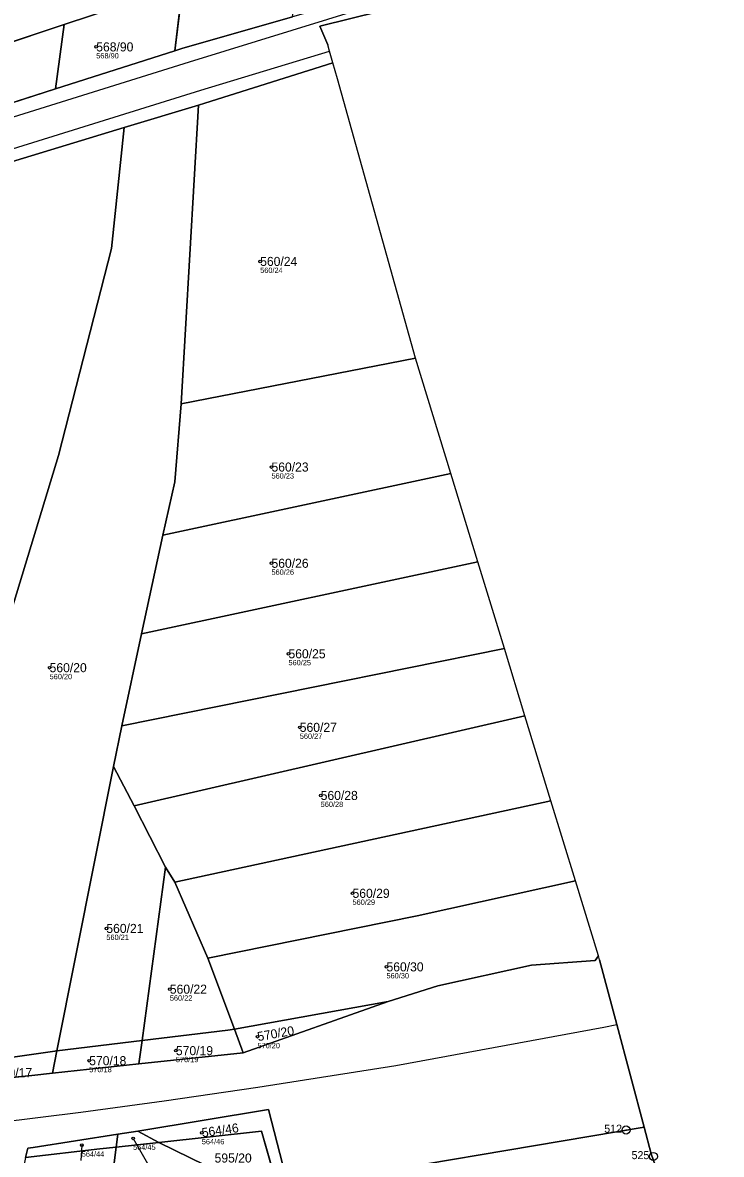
# Model space of a CAD drawing. Extents: x -732749 to -730903, y -1025757 to -1023435.
# Drawn here: x -731348.6 to -731217.7, y -1024807.5 to -1024595.4 of the extents above; entities that cross this region are included whole.
import ezdxf

# ---------------------------------------------------------------- set-up
doc = ezdxf.new("R2010")
doc.units = 0
for name, color, linetype in [('Definiční body', 7, 'Continuous'), ('Hranice parcel', 7, 'Continuous'), ('Parcelní čísla', 7, 'Continuous'), ('Polygon ku', 7, 'Continuous'), ('Polygon parcely', 7, 'Continuous'), ('Pop  PČ popisy', 7, 'Continuous'), ('Poz předměty', 7, 'Continuous'), ('Vnitřní kresba', 7, 'Continuous'), ('Značky bodu BP', 7, 'Continuous')]:
    doc.layers.add(name, color=color, linetype=linetype)

msp = doc.modelspace()

# ---------------------------------------------------------------- linework, layer by layer
at = {"layer": 'Definiční body'}
for centre in [(-731334.82, -1024599.96), (-731304.1, -1024640.16), (-731301.98, -1024678.69), (-731301.98, -1024696.72), (-731298.8, -1024713.68), (-731343.56, -1024716.29), (-731296.68, -1024727.47), (-731292.76, -1024740.23), (-731286.79, -1024758.57), (-731332.93, -1024765.15), (-731280.43, -1024772.35), (-731321.03, -1024776.53), (-731304.62, -1024785.44), (-731319.89, -1024788.05), (-731336.14, -1024789.93), (-731315.04, -1024803.44), (-731327.92, -1024804.49), (-731337.54, -1024805.77)]:
    msp.add_circle(centre, 0.25, dxfattribs=at)
at = {"layer": 'Hranice parcel'}
for p, q in [((-731340.83, -1024595.77), (-731320.55, -1024589.04)), ((-731320.09, -1024600.67), (-731318.62, -1024588.44)), ((-731298.04, -1024594.31), (-731318.77, -1024600.25)), ((-731361.64, -1024602.68), (-731340.83, -1024595.77)), ((-731342.46, -1024607.84), (-731340.83, -1024595.77)), ((-731292.9, -1024596.1), (-731291.4, -1024599.6)), ((-731320.09, -1024600.67), (-731342.46, -1024607.84)), ((-731318.77, -1024600.25), (-731320.09, -1024600.67)), ((-731314.47, -1024610.5), (-731290.46, -1024602.97)), ((-731289.63, -1024605.94), (-731290.46, -1024602.97)), ((-731275, -1024658.3), (-731289.63, -1024605.94)), ((-731342.46, -1024607.84), (-731363.18, -1024614.48)), ((-731329.57, -1024615.08), (-731315.68, -1024610.87)), ((-731318.88, -1024666.84), (-731315.68, -1024610.87)), ((-731315.68, -1024610.87), (-731314.47, -1024610.5)), ((-731275, -1024658.3), (-731318.88, -1024666.84)), ((-731268.38, -1024679.93), (-731275, -1024658.3)), ((-731322.32, -1024691.46), (-731268.38, -1024679.93)), ((-731263.32, -1024696.44), (-731268.38, -1024679.93)), ((-731326.35, -1024709.93), (-731322.32, -1024691.46)), ((-731263.32, -1024696.44), (-731326.35, -1024709.93)), ((-731258.34, -1024712.69), (-731263.32, -1024696.44)), ((-731330.02, -1024727.2), (-731326.35, -1024709.93)), ((-731330.02, -1024727.2), (-731258.34, -1024712.69)), ((-731254.48, -1024725.29), (-731258.34, -1024712.69)), ((-731327.73, -1024742.16), (-731254.48, -1024725.29)), ((-731249.6, -1024741.23), (-731254.48, -1024725.29)), ((-731331.6, -1024734.81), (-731330.02, -1024727.2)), ((-731342.2, -1024788.09), (-731331.6, -1024734.81)), ((-731327.73, -1024742.16), (-731331.6, -1024734.81)), ((-731320.09, -1024756.5), (-731249.6, -1024741.23)), ((-731245.01, -1024756.21), (-731249.6, -1024741.23)), ((-731321.84, -1024753.69), (-731327.73, -1024742.16)), ((-731326.23, -1024786.17), (-731321.84, -1024753.69)), ((-731320.09, -1024756.5), (-731321.84, -1024753.69)), ((-731313.93, -1024770.71), (-731320.09, -1024756.5)), ((-731240.7, -1024770.3), (-731245.01, -1024756.21)), ((-731308.92, -1024784.01), (-731313.93, -1024770.71)), ((-731240.5, -1024771.06), (-731240.7, -1024770.3)), ((-731240.5, -1024771.06), (-731237.27, -1024783.17)), ((-731308.92, -1024784.01), (-731280.11, -1024778.84)), ((-731280.11, -1024778.84), (-731307.26, -1024788.44)), ((-731326.23, -1024786.17), (-731310.19, -1024784.24)), ((-731310.19, -1024784.24), (-731308.92, -1024784.01)), ((-731307.26, -1024788.44), (-731308.92, -1024784.01)), ((-731237.27, -1024783.17), (-731232.14, -1024802.38)), ((-731342.2, -1024788.09), (-731326.23, -1024786.17)), ((-731326.82, -1024790.53), (-731326.23, -1024786.17)), ((-731343.03, -1024792.27), (-731342.2, -1024788.09)), ((-731307.26, -1024788.44), (-731326.82, -1024790.53)), ((-731326.82, -1024790.53), (-731343.03, -1024792.27)), ((-731346.88, -1024792.68), (-731370.02, -1024795.11)), ((-731343.03, -1024792.27), (-731346.88, -1024792.68)), ((-731330.8, -1024803.72), (-731327.03, -1024803.13)), ((-731323.1, -1024805.24), (-731327.03, -1024803.13)), ((-731323.1, -1024805.24), (-731303.84, -1024803.13)), ((-731303.84, -1024803.13), (-731300.76, -1024813.97)), ((-731232.14, -1024802.38), (-731298.8, -1024813.64)), ((-731331.11, -1024806.12), (-731330.8, -1024803.72)), ((-731331.11, -1024806.12), (-731323.1, -1024805.24)), ((-731299.88, -1024816.64), (-731323.1, -1024805.24)), ((-731334.18, -1024806.46), (-731348.06, -1024808.05)), ((-731331.11, -1024806.12), (-731334.18, -1024806.46))]:
    msp.add_line(p, q, dxfattribs=at)
for points in [[(-731000.56, -1024491.5), (-731019.19, -1024499.94), (-731038.5, -1024508.7), (-731067.06, -1024522.46), (-731108.1, -1024540.6), (-731132.9, -1024550.8), (-731231, -1024580.7), (-731292.9, -1024596.1)], [(-731290.46, -1024602.97), (-731291.08, -1024600.75), (-731291.4, -1024599.6)], [(-731329.57, -1024615.08), (-731360.81, -1024624.55), (-731373.64, -1024628.52)], [(-731369.39, -1024791.96), (-731354.94, -1024719.31), (-731341.91, -1024676.51), (-731331.96, -1024637.77), (-731329.57, -1024615.08)], [(-731322.32, -1024691.46), (-731320.12, -1024681.47), (-731318.88, -1024666.84)], [(-731313.93, -1024770.71), (-731274.67, -1024762.8), (-731245.01, -1024756.21)], [(-731240.7, -1024770.3), (-731241.32, -1024771.18), (-731253.24, -1024772.02), (-731270.83, -1024775.92), (-731280.11, -1024778.84)], [(-731369.39, -1024791.96), (-731342.59, -1024788.14), (-731342.37, -1024788.11), (-731342.2, -1024788.09)], [(-731327.03, -1024803.13), (-731302.56, -1024799.1), (-731298.8, -1024813.64)], [(-731232.14, -1024802.38), (-731230.8, -1024807.4), (-731228.6, -1024813.75)], [(-731348.06, -1024808.05), (-731347.62, -1024806.31), (-731346.66, -1024806.21), (-731330.8, -1024803.72)], [(-731332.37, -1024827.26), (-731333.74, -1024826.75), (-731331.11, -1024806.12)]]:
    msp.add_lwpolyline(points, dxfattribs=at)
at = {"layer": 'Polygon ku'}
msp.add_lwpolyline([(-731228.6, -1024813.75), (-731230.8, -1024807.4), (-731232.14, -1024802.38), (-731237.27, -1024783.17), (-731240.5, -1024771.06), (-731240.7, -1024770.3), (-731245.01, -1024756.21), (-731249.6, -1024741.23), (-731254.48, -1024725.29), (-731258.34, -1024712.69), (-731263.32, -1024696.44), (-731268.38, -1024679.93), (-731275, -1024658.3), (-731289.63, -1024605.94), (-731290.46, -1024602.97), (-731291.08, -1024600.75), (-731291.4, -1024599.6), (-731292.9, -1024596.1), (-731231, -1024580.7), (-731132.9, -1024550.8)], dxfattribs=at)
at = {"layer": 'Polygon parcely'}
for points in [[(-731396.92, -1024430.73), (-731405.68, -1024487.75), (-731408.32, -1024539.25), (-731411.17, -1024556.07), (-731428.58, -1024623.59), (-731409.79, -1024619.61), (-731404.24, -1024617.64), (-731379.95, -1024609.03), (-731367.75, -1024604.71), (-731361.64, -1024602.68), (-731340.83, -1024595.77), (-731320.55, -1024589.04), (-731296.11, -1024580.48), (-731268.95, -1024570.98), (-731263.25, -1024568.98), (-731247.73, -1024563.81), (-731245.2, -1024560.99), (-731237.03, -1024551.86), (-731219.11, -1024538.09), (-731199.3, -1024513.61)], [(-731507.81, -1024670.47), (-731487.83, -1024663.94), (-731481.06, -1024661.72), (-731464.74, -1024656.68), (-731440.17, -1024649.08), (-731417.24, -1024641.99), (-731416.66, -1024639.33), (-731394.43, -1024632.88), (-731394.88, -1024635.08), (-731373.64, -1024628.52), (-731360.81, -1024624.55), (-731329.57, -1024615.08), (-731315.68, -1024610.87), (-731314.47, -1024610.5), (-731290.46, -1024602.97), (-731291.08, -1024600.75), (-731291.4, -1024599.6), (-731292.9, -1024596.1), (-731231, -1024580.7), (-731132.9, -1024550.8)], [(-731200.51, -1024564.65), (-731223.17, -1024571.11), (-731236.65, -1024574.96), (-731247.44, -1024578.5), (-731271.49, -1024586.39), (-731279.07, -1024588.88), (-731298.04, -1024594.31), (-731318.77, -1024600.25), (-731320.09, -1024600.67), (-731342.46, -1024607.84), (-731363.18, -1024614.48), (-731364.5, -1024614.9), (-731381.78, -1024620.45), (-731406.87, -1024628.5), (-731418.04, -1024632.08), (-731431.49, -1024635.93), (-731452.35, -1024641.89), (-731458.9, -1024643.76), (-731474.7, -1024648.82), (-731495.41, -1024655.45), (-731510.51, -1024660.29)], [(-731348.06, -1024808.05), (-731347.62, -1024806.31), (-731346.66, -1024806.21), (-731330.8, -1024803.72), (-731327.03, -1024803.13), (-731302.56, -1024799.1), (-731298.8, -1024813.64), (-731232.14, -1024802.38), (-731237.27, -1024783.17), (-731240.5, -1024771.06), (-731240.7, -1024770.3), (-731241.32, -1024771.18), (-731253.24, -1024772.02), (-731270.83, -1024775.92), (-731280.11, -1024778.84), (-731307.26, -1024788.44), (-731326.82, -1024790.53), (-731343.03, -1024792.27), (-731346.88, -1024792.68), (-731370.02, -1024795.11)]]:
    msp.add_lwpolyline(points, dxfattribs=at)
for points in [[(-731296.25, -1024581.49), (-731318.62, -1024588.44), (-731320.09, -1024600.67), (-731318.77, -1024600.25), (-731298.04, -1024594.31)], [(-731318.62, -1024588.44), (-731320.55, -1024589.04), (-731340.83, -1024595.77), (-731342.46, -1024607.84), (-731320.09, -1024600.67)], [(-731342.46, -1024607.84), (-731340.83, -1024595.77), (-731361.64, -1024602.68), (-731363.18, -1024614.48)], [(-731275, -1024658.3), (-731289.63, -1024605.94), (-731290.46, -1024602.97), (-731314.47, -1024610.5), (-731315.68, -1024610.87), (-731318.88, -1024666.84)], [(-731342.2, -1024788.09), (-731331.6, -1024734.81), (-731330.02, -1024727.2), (-731326.35, -1024709.93), (-731322.32, -1024691.46), (-731320.12, -1024681.47), (-731318.88, -1024666.84), (-731315.68, -1024610.87), (-731329.57, -1024615.08), (-731331.96, -1024637.77), (-731341.91, -1024676.51), (-731354.94, -1024719.31), (-731369.39, -1024791.96), (-731342.59, -1024788.14), (-731342.37, -1024788.11)], [(-731369.79, -1024792.02), (-731369.39, -1024791.96), (-731354.94, -1024719.31), (-731341.91, -1024676.51), (-731331.96, -1024637.77), (-731329.57, -1024615.08), (-731360.81, -1024624.55), (-731373.64, -1024628.52), (-731374.96, -1024636.49), (-731382.25, -1024668.49), (-731399.92, -1024749.24), (-731405.96, -1024777.18), (-731409.81, -1024794.03), (-731398.19, -1024792.52)], [(-731268.38, -1024679.93), (-731275, -1024658.3), (-731318.88, -1024666.84), (-731320.12, -1024681.47), (-731322.32, -1024691.46)], [(-731263.32, -1024696.44), (-731268.38, -1024679.93), (-731322.32, -1024691.46), (-731326.35, -1024709.93)], [(-731258.34, -1024712.69), (-731263.32, -1024696.44), (-731326.35, -1024709.93), (-731330.02, -1024727.2)], [(-731254.48, -1024725.29), (-731258.34, -1024712.69), (-731330.02, -1024727.2), (-731331.6, -1024734.81), (-731327.73, -1024742.16)], [(-731249.6, -1024741.23), (-731254.48, -1024725.29), (-731327.73, -1024742.16), (-731321.84, -1024753.69), (-731320.09, -1024756.5)], [(-731321.84, -1024753.69), (-731327.73, -1024742.16), (-731331.6, -1024734.81), (-731342.2, -1024788.09), (-731326.23, -1024786.17)], [(-731245.01, -1024756.21), (-731249.6, -1024741.23), (-731320.09, -1024756.5), (-731313.93, -1024770.71), (-731274.67, -1024762.8)], [(-731308.92, -1024784.01), (-731313.93, -1024770.71), (-731320.09, -1024756.5), (-731321.84, -1024753.69), (-731326.23, -1024786.17), (-731310.19, -1024784.24)], [(-731240.7, -1024770.3), (-731245.01, -1024756.21), (-731274.67, -1024762.8), (-731313.93, -1024770.71), (-731308.92, -1024784.01), (-731280.11, -1024778.84), (-731270.83, -1024775.92), (-731253.24, -1024772.02), (-731241.32, -1024771.18)], [(-731307.26, -1024788.44), (-731280.11, -1024778.84), (-731308.92, -1024784.01)], [(-731307.26, -1024788.44), (-731308.92, -1024784.01), (-731310.19, -1024784.24), (-731326.23, -1024786.17), (-731326.82, -1024790.53)], [(-731326.23, -1024786.17), (-731342.2, -1024788.09), (-731343.03, -1024792.27), (-731326.82, -1024790.53)], [(-731342.2, -1024788.09), (-731342.37, -1024788.11), (-731342.59, -1024788.14), (-731369.39, -1024791.96), (-731370.02, -1024795.11), (-731346.88, -1024792.68), (-731343.03, -1024792.27)], [(-731323.1, -1024805.24), (-731303.84, -1024803.13), (-731300.76, -1024813.97), (-731298.8, -1024813.64), (-731302.56, -1024799.1), (-731327.03, -1024803.13)], [(-731323.1, -1024805.24), (-731327.03, -1024803.13), (-731330.8, -1024803.72), (-731331.11, -1024806.12)], [(-731299.88, -1024816.64), (-731300.76, -1024813.97), (-731303.84, -1024803.13), (-731323.1, -1024805.24)], [(-731300.76, -1024813.97), (-731299.88, -1024816.64), (-731296.44, -1024827.15), (-731294.01, -1024826.84), (-731228.6, -1024813.75), (-731230.8, -1024807.4), (-731232.14, -1024802.38), (-731298.8, -1024813.64)], [(-731330.8, -1024803.72), (-731346.66, -1024806.21), (-731347.62, -1024806.31), (-731348.06, -1024808.05), (-731334.18, -1024806.46), (-731331.11, -1024806.12)], [(-731299.88, -1024816.64), (-731323.1, -1024805.24), (-731331.11, -1024806.12), (-731333.74, -1024826.75), (-731332.37, -1024827.26), (-731291.14, -1024846.23), (-731295.29, -1024830.69), (-731296.44, -1024827.15)], [(-731374.34, -1024937.46), (-731356.44, -1024941.69), (-731352.12, -1024927.24), (-731348.72, -1024912.77), (-731345.62, -1024896.67), (-731342.59, -1024881.5), (-731335.27, -1024850.07), (-731332.37, -1024827.26), (-731333.74, -1024826.75), (-731331.11, -1024806.12), (-731334.18, -1024806.46), (-731348.06, -1024808.05)]]:
    msp.add_lwpolyline(points, close=True, dxfattribs=at)
at = {"layer": 'Pop  PČ popisy'}
for p, q in [((-731327.92, -1024804.49), (-731326.7, -1024806.58)), ((-731337.54, -1024805.77), (-731337.7, -1024808.62)), ((-731326.7, -1024806.58), (-731325.2, -1024809.18))]:
    msp.add_line(p, q, dxfattribs=at)
at = {"layer": 'Poz předměty'}
for p, q in [((-731278.68, -1024790.84), (-731239.67, -1024783.62)), ((-731239.67, -1024783.62), (-731237.27, -1024783.17)), ((-731304.55, -1024794.88), (-731278.68, -1024790.84)), ((-731322.07, -1024797.44), (-731304.55, -1024794.88)), ((-731337.72, -1024799.57), (-731322.07, -1024797.44)), ((-731360.83, -1024802.41), (-731337.72, -1024799.57))]:
    msp.add_line(p, q, dxfattribs=at)
at = {"layer": 'Vnitřní kresba'}
for p, q in [((-731317.34, -1024602.76), (-731278.86, -1024590.82)), ((-731315.23, -1024608.09), (-731291.08, -1024600.75)), ((-731363.54, -1024617.22), (-731317.34, -1024602.76)), ((-731361.97, -1024622.65), (-731315.23, -1024608.09))]:
    msp.add_line(p, q, dxfattribs=at)
at = {"layer": 'Značky bodu BP'}
for centre, radius in [((-731235.53, -1024802.92), 0.75), ((-731235.53, -1024802.92), 0.03), ((-731230.41, -1024807.88), 0.75)]:
    msp.add_circle(centre, radius, dxfattribs=at)

# ---------------------------------------------------------------- texts
at = {"layer": 'Definiční body'}
for s, p in [('568/90', (-731334.82, -1024602.12)), ('560/24', (-731304.1, -1024642.32)), ('560/23', (-731301.98, -1024680.85)), ('560/26', (-731301.98, -1024698.88)), ('560/25', (-731298.8, -1024715.84)), ('560/20', (-731343.56, -1024718.45)), ('560/27', (-731296.68, -1024729.63)), ('560/28', (-731292.76, -1024742.39)), ('560/29', (-731286.79, -1024760.73)), ('560/21', (-731332.93, -1024767.31)), ('560/30', (-731280.43, -1024774.51)), ('560/22', (-731321.03, -1024778.69)), ('570/20', (-731304.62, -1024787.6)), ('570/19', (-731319.89, -1024790.21)), ('570/18', (-731336.14, -1024792.09)), ('564/46', (-731315.04, -1024805.6)), ('564/44', (-731337.54, -1024807.93)), ('564/45', (-731327.92, -1024806.65))]:
    msp.add_text(s, height=1, dxfattribs=at).set_placement(p)
at = {"layer": 'Parcelní čísla'}
for s, p in [('568/90', (-731334.82, -1024600.81)), ('560/24', (-731304.1, -1024641.01)), ('560/23', (-731301.98, -1024679.54)), ('560/26', (-731301.98, -1024697.57)), ('560/25', (-731298.8, -1024714.53)), ('560/20', (-731343.56, -1024717.14)), ('560/27', (-731296.68, -1024728.32)), ('560/28', (-731292.76, -1024741.08)), ('560/29', (-731286.79, -1024759.42)), ('560/21', (-731332.93, -1024766)), ('560/30', (-731280.43, -1024773.2)), ('560/22', (-731321.03, -1024777.38)), ('570/19', (-731319.89, -1024788.9)), ('570/18', (-731336.14, -1024790.78)), ('570/17', (-731353.79, -1024793.03)), ('595/20', (-731312.64, -1024809.02))]:
    msp.add_text(s, height=1.7, dxfattribs=at).set_placement(p)
for s, rotation, p in [('570/20', 10, (-731304.47, -1024786.28)), ('564/46', 8, (-731314.92, -1024804.28))]:
    msp.add_text(s, height=1.7, rotation=rotation, dxfattribs=at).set_placement(p)
at = {"layer": 'Značky bodu BP'}
for s, p in [('512', (-731239.63, -1024803.42)), ('525', (-731234.51, -1024808.38))]:
    msp.add_text(s, height=1.5, dxfattribs=at).set_placement(p)

doc.saveas('drawing.dxf')
